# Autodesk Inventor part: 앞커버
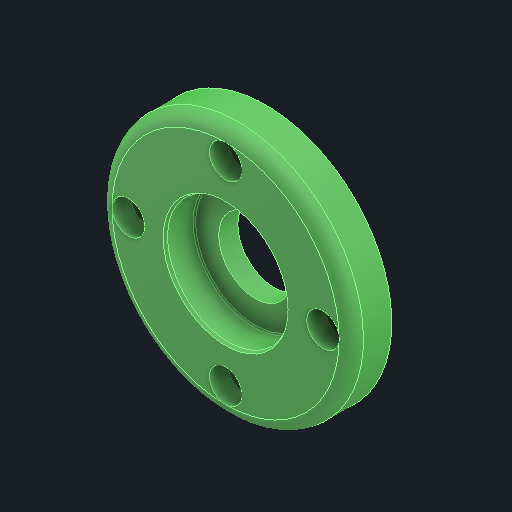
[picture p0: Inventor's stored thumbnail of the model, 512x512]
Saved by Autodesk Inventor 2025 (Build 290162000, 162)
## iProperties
Created: 2025-08
Part Number: 앞커버
Material: 알루미늄 6061
Document SubType Name: Modeling
Designer: infra14
Density: 2.71 g/cm^3
Appearance: 기본값
Author: jhkim
Sending System: Autodesk Inventor 2026
Preprocessor: ST-DEVELOPER v20.1
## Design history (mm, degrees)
feature "솔리드1"
node "솔리드2"
